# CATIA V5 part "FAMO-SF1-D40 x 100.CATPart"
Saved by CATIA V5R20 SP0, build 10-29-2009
Part number: FAMO-SF1-D40 x 100
Definition: NONE
Nomenclature: FAMO-SF1-D40 x 100
Source: Unknown
Description: FAMO-SF1-D40 x 100
Bounding box of the stored display mesh (mm): x -53 to 47, y -31.5 to 31.5, z -31.5 to 31.5
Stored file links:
  C:\Users\Utente\Desktop\IO LAVORO\3D X SITO CF\X SITO\FAMO\FAMO-SF1-D40 x 100.CATPart
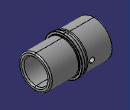
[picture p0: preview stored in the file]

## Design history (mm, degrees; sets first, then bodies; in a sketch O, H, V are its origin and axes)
Body1 "FAMO-SF1-D40 x 100" (main body)
  Solid1: solid without history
